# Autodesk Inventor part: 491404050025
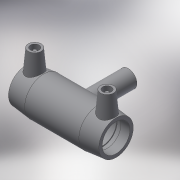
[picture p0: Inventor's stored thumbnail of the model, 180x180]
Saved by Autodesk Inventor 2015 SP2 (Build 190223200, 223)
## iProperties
Created: 2017-06
Part Number: 491404050025
Material: Generic
Description: PLASSON REDUCING TEE 50x25x50
Document SubType Name: Modeling
Designer: KIM
Mass: 57.3761 g
Surface Area: 241.06 cm^2
Volume: 57.3761 cm^3
Density: 1 g/cm^3
Appearance: Default
Author: KIM
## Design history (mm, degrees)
derived "491404.ipt"
feature "Solid1::491404.ipt"
tag "TaggingFeature1"
body "Solid1"
other parameters: "d0" = 139, "d2" = 68, "d3" = 48, "d4" = 27.8, "d5" = 61.2, "d6" = 47.5, "d8" = 168 deg, "d10" = 19.2, "d11" = 6.4, "d13" = 139, "d14" = 17.6296, "d17" = 45, "d19" = 3.52592, "d20" = 168 deg, "d22" = 63.24, "d23" = 68, "d25" = 135 deg, "d26" = 97.3, "d29" = 52, "d30" = 15, "d31" = 55.6, "d34" = 5 deg, "d35" = 15, "d39" = 5 deg, "d41" = 4, "d42" = 14, "d43" = 0, "d45" = 4, "d46" = 6, "d47" = 0, "d48" = -78, "d49" = 25, "d51" = 0, "d54" = 0, "d55" = 61.2, "d56" = 68, "d57" = 48.65, "d58" = 135 deg, "d59" = 48, "d60" = 48, "d61" = 135 deg, "d62" = 78, "d72" = 63.245, "d73" = 31.6225, "d74" = -78, "d75" = 26.25, "d77" = 0, "d80" = 0, "d81" = 25, "d82" = 44, "d83" = 0, "d84" = 3, "d85" = 0, "d86" = 16, "d87" = 61.9752, "d88" = 6.4, "d89" = 3, "d90" = 0, "L_" = 139, "L_1" = 48, "D_" = 68, "A_" = 52, "d_2" = 12, "H_" = 78, "d_1" = 25
